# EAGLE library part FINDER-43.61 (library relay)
Low profile PCB relays 10 - 16 A FINDER 43 Series Kontakt max. AC- 250V, Strom - Kontakt AC- max. 10A 5 mm contact pin pitch, 1 Pole NO, 16 A, PCB mount Distributor: FARNELL Source: http://www.farnell.com/datasheets/87682.pdf
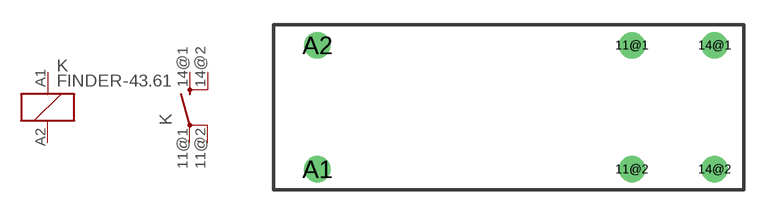
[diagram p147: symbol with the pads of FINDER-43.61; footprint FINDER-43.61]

Designator prefix K; gates K=K -1=S-X2

## FINDER-43.61 (OC_FARNELL: unknown; OC_NEWARK: unknown)  [FINDER-43.61]
11@1  -1:PA  pas
11@2  -1:PB  pas
14@1  -1:SA  pas
14@2  -1:SB  pas
A1  K:1  pas
A2  K:2  pas

## Footprint FINDER-43.61 (pad centres in mm)
Low profile PCB relays 10 - 16 A FINDER 43 Series Kontakt max. AC- 250V, Strom - Kontakt AC- max. 10A 5 mm contact pin pitch, 1 Pole NO, 16 A, PCB mount Distributor: FARNELL Source: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
drill 1 pad 1.6 round: 11@1 0,3.75; 11@2 0,-3.75; 14@1 5,3.75; 14@2 5,-3.75; A1 -19,-3.75; A2 -19,3.75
